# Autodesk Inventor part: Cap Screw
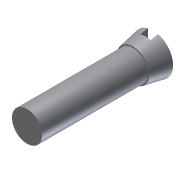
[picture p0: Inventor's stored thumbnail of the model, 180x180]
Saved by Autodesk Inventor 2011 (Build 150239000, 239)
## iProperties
Shininess: 77.0
Length Units: 11269
Angle Units: 11279
Time Units: 11290
Mass Units: 11283
Length Display Precision: 3
Angle Display Precision: 2
Created: 2002-02
Part Number: Cap Screw
Document SubType Name: Modeling
Designer: ***
Density: 1 g/cm^3
Density: 0.0
Volumn: 0.0
Area: 0.0
PropertySet Name: Model Information
Control State: 0
Master: False
Checked Out: False
Author: ***
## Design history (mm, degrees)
sketch "Sketch1"
  geometry: L1 (0, 27.83)-(4, 27.83); L2 (4, 27.83)-(3.25, 23.83); L3 (3.25, 23.83)-(0, 23.83); L4 (0, 23.83)-(0, 27.83)
  constraints: 8 end point, 1 horizontal, 1 parallel, 1 perpendicular, 1 point on line
  dimensions: "d2" = 4 distance from line of L1 L2.end; "d5" = 8 diameter of L1.end L4; "d6" = 6.5 diameter of L3.start L4; "d14" = 4 distance of L3.end L1.start
revolve "Revolution1" sketch "Sketch1" stored, may be unused: angle "d7" = 90 deg
sketch "Sketch2"
  geometry: C1 r 3 at (0, 0)
  constraints: 1 centre point
  dimensions: "d8" = 6 diameter of C1
extrude "Extrusion1" join sketch "Sketch2" distance "d9" = 21; taper "d10" = 0 deg
sketch "Sketch3"
  geometry: L1 (-1, 28.967)-(1, 28.967); L2 (1, 28.967)-(1, 26.33); L3 (1, 26.33)-(-1, 26.33); L4 (-1, 26.33)-(-1, 28.967); L5 (-4, 27.83)-(4, 27.83) reference
  constraints: 8 end point, 2 parallel, 1 horizontal, 1 perpendicular
  dimensions: "d11" = 2 distance of L1.start L1.end; "d15" = 1.5 distance between parallel lines of L5 L3
extrude "Extrusion2" cut sketch "Sketch3" stored distance "d12" = 24; taper "d13" = 0 deg
body "Solid1"
